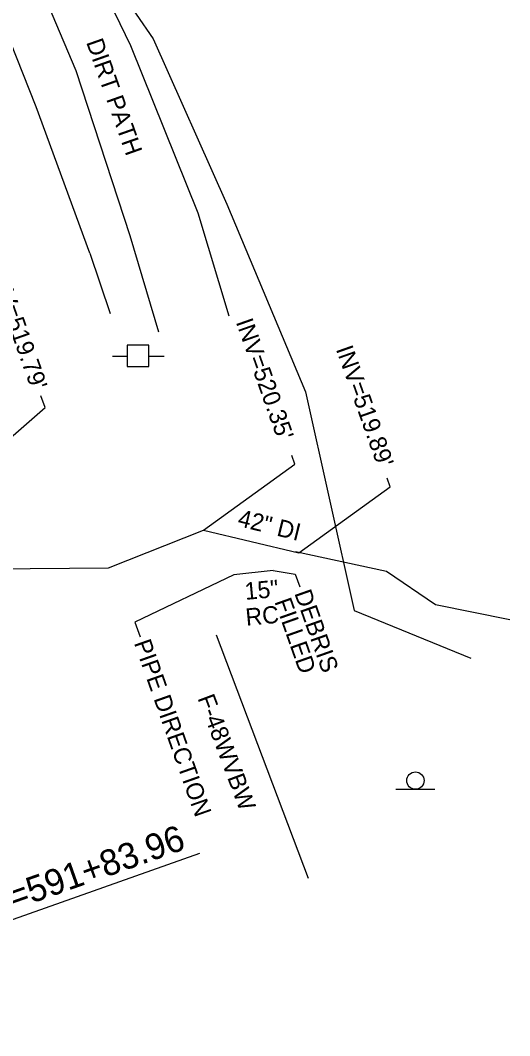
# Model space of a CAD drawing. Extents: x 2004847 to 2009016, y 1134161 to 1140101.
# Drawn here: x 2007047.7 to 2007161.1, y 1134167.7 to 1134403 of the extents above; entities that cross this region are included whole.
import ezdxf

# ---------------------------------------------------------------- set-up
doc = ezdxf.new("R2010")
doc.units = 0
for name, color, linetype in [('RD_EX_BldgApp', 7, 'Continuous'), ('RD_EX_DR_Pipe', 7, 'Continuous'), ('RD_EX_Driveway', 7, 'Continuous'), ('RD_EX_Fence_Other', 7, 'Continuous'), ('RD_EX_H2O', 7, 'Continuous'), ('RD_EX_UT', 7, 'Continuous'), ('RD_EX_VEG', 7, 'Continuous'), ('RD_HC_Data', 7, 'Continuous'), ('RD_Sketch1', 7, 'Continuous'), ('RD_Sketch3', 7, 'Continuous')]:
    doc.layers.add(name, color=color, linetype=linetype)

msp = doc.modelspace()

# ---------------------------------------------------------------- linework, layer by layer
at = {"layer": 'RD_EX_BldgApp'}
msp.add_line((2007134.72, 1134224.82), (2007143.72, 1134224.82), dxfattribs=at)
msp.add_circle((2007139.23, 1134226.84), 2, dxfattribs=at)
at = {"layer": 'RD_EX_DR_Pipe'}
for p, q in [((2007090.11, 1134284.86), (2007112.22, 1134279.63)), ((2007106.27, 1134275.51), (2007097.14, 1134274.52))]:
    msp.add_line(p, q, dxfattribs=at)
at = {"layer": 'RD_EX_Driveway'}
for points in [[(2007047.24, 1134476.04), (2007054.6, 1134435.72), (2007073.17, 1134397.21), (2007088.83, 1134358.42), (2007096.03, 1134334.59)], [(2007079.8, 1134330.74), (2007073.16, 1134353.09), (2007060.64, 1134391.35), (2007044.77, 1134428.83), (2007030.28, 1134471.18)]]:
    msp.add_lwpolyline(points, dxfattribs=at)
at = {"layer": 'RD_EX_Fence_Other'}
for p, q in [((2007063.77, 1134349.09), (2007068.49, 1134335.09)), ((2007093.03, 1134260.61), (2007114.35, 1134204.22))]:
    msp.add_line(p, q, dxfattribs=at)
msp.add_lwpolyline([(2007063.77, 1134349.09), (2007051.32, 1134382.98), (2007034.66, 1134424.99), (2007022.46, 1134465.49), (2007009.27, 1134502.08), (2006987.27, 1134565.71), (2006982.09, 1134580.37), (2006971.28, 1134619.61), (2006967.26, 1134636.51), (2006955.53, 1134679.01), (2006933.1, 1134763.45), (2006921.61, 1134808.45), (2006913.35, 1134838.48), (2006889.85, 1134911.88), (2006879.83, 1134940.33), (2006864.22, 1134985.13), (2006847.99, 1135029.35), (2006842.47, 1135045.23)], dxfattribs=at)
at = {"layer": 'RD_EX_H2O'}
for points in [[(2007023.1, 1134286.67), (2007035.85, 1134288.26), (2007040.81, 1134275.94), (2007068.13, 1134276.18), (2007090.11, 1134284.87)], [(2007111.41, 1134279.91), (2007132.49, 1134275.35), (2007143.89, 1134267.67), (2007161.07, 1134264.18)]]:
    msp.add_lwpolyline(points, dxfattribs=at)
at = {"layer": 'RD_EX_UT'}
for p, q in [((2007077.44, 1134327.79), (2007072.44, 1134327.79)), ((2007072.44, 1134327.79), (2007072.44, 1134322.79)), ((2007077.44, 1134327.79), (2007072.44, 1134327.79)), ((2007072.44, 1134327.79), (2007072.44, 1134322.79)), ((2007077.44, 1134327.79), (2007072.44, 1134327.79)), ((2007072.44, 1134327.79), (2007072.44, 1134322.79)), ((2007077.44, 1134322.79), (2007077.44, 1134327.79)), ((2007077.44, 1134322.79), (2007077.44, 1134327.79)), ((2007077.44, 1134322.79), (2007077.44, 1134327.79)), ((2007069.01, 1134325.23), (2007072.48, 1134325.23)), ((2007069.01, 1134325.23), (2007072.48, 1134325.23)), ((2007069.01, 1134325.23), (2007072.48, 1134325.23)), ((2007077.37, 1134325.23), (2007081.01, 1134325.23)), ((2007077.37, 1134325.23), (2007081.01, 1134325.23)), ((2007077.37, 1134325.23), (2007081.01, 1134325.23)), ((2007072.44, 1134322.79), (2007077.44, 1134322.79)), ((2007072.44, 1134322.79), (2007077.44, 1134322.79)), ((2007072.44, 1134322.79), (2007077.44, 1134322.79))]:
    msp.add_line(p, q, dxfattribs=at)
at = {"layer": 'RD_EX_VEG'}
for points in [[(2007060.61, 1134514.95), (2007047.76, 1134472.69), (2007054.79, 1134433.13), (2007078.46, 1134398.75), (2007095.56, 1134360.4)], [(2007095.56, 1134360.4), (2007113.74, 1134316.97), (2007125, 1134266.23), (2007152.04, 1134255.18)]]:
    msp.add_lwpolyline(points, dxfattribs=at)
at = {"layer": 'RD_HC_Data'}
msp.add_line((2006969.76, 1134167.71), (2007089.24, 1134209.98), dxfattribs=at)
at = {"layer": 'RD_Sketch1'}
for points in [[(2007022.9, 1134286.65), (2007053.4, 1134313.31), (2007052.46, 1134315.98)], [(2007090.11, 1134284.86), (2007111.28, 1134300.15), (2007110.57, 1134302.16)], [(2007112.22, 1134279.63), (2007133.39, 1134294.91), (2007132.68, 1134296.92)], [(2007097.14, 1134274.52), (2007074.22, 1134263.59), (2007075.44, 1134260.16)], [(2007106.27, 1134275.51), (2007111.39, 1134274.7), (2007112.44, 1134271.72)]]:
    msp.add_lwpolyline(points, dxfattribs=at)

# ---------------------------------------------------------------- texts
at = {"layer": 'RD_HC_Data'}
msp.add_text('POT=591+83.96', height=6, rotation=19.482, dxfattribs=at).set_placement((2007030.37, 1134191.28))
at = {"layer": 'RD_Sketch1'}
for s, rotation, p in [("INV=519.79'", 289.4494, (2007040.5, 1134344.76)), ("INV=520.35'", 289.4494, (2007097.57, 1134333.13)), ("INV=519.89'", 289.4494, (2007120.75, 1134326.85)), ('42" DI', 346.0643, (2007097.82, 1134285.9)), ('15"', 5.2856, (2007099.85, 1134268.71)), ('FILLED', 289.4494, (2007106.51, 1134268.34)), ('DEBRIS', 289.4494, (2007111.13, 1134270.28)), ('RC', 5.2856, (2007100.05, 1134262.71)), ('PIPE DIRECTION', 289.4494, (2007073.96, 1134258.74))]:
    msp.add_text(s, height=4, rotation=rotation, dxfattribs=at).set_placement(p)
at = {"layer": 'RD_Sketch3'}
for s, rotation, p in [('DIRT PATH', 289.4494, (2007062.89, 1134397.99)), ('F-48WVBW', 290.5226, (2007088.7, 1134245.95))]:
    msp.add_text(s, height=4, rotation=rotation, dxfattribs=at).set_placement(p)

doc.saveas('drawing.dxf')
